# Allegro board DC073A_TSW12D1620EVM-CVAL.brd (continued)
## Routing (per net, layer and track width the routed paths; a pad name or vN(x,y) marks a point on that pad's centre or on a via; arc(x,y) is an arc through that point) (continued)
DID4-: length 81.3
  L08_SIG2 w0.076: v1(85.22,93.6) 85.22,94.01 85.34,94.13 85.66,94.13 86.04,94.51 86.04,99.3 87.83,101.09 99.63,101.09 102.03,98.69 104.28,98.69 104.57,98.99 104.57,99.73 104.72,99.89 105.26,99.89 105.41,99.73 105.41,98.99 105.7,98.69 106.44,98.69 106.73,98.99 106.73,99.73 106.88,99.89 107.42,99.89 107.57,99.73 107.57,98.99 107.86,98.69 108.6,98.69 108.89,98.99 108.89,99.73 109.04,99.89 109.58,99.89 109.73,99.73 109.73,98.99 110.02,98.69 110.76,98.69 111.05,98.99 111.05,99.73 111.2,99.89 111.74,99.89 111.89,99.73 111.89,98.99 112.18,98.69 112.91,98.69 113.21,98.99 113.21,99.73 113.36,99.89 113.89,99.89 114.05,99.73 114.05,98.99 114.34,98.69 115.07,98.69 115.37,98.99 115.37,99.73 115.52,99.89 116.05,99.89 116.21,99.73 116.21,98.99 116.5,98.69 117.23,98.69 117.53,98.99 117.53,99.73 117.68,99.89 118.21,99.89 118.36,99.73 118.36,98.99 118.66,98.69 119.39,98.69 119.69,98.99 119.69,99.73 119.84,99.89 120.37,99.89 120.52,99.73 120.52,98.99 120.82,98.69 121.55,98.69 121.84,98.99 121.84,99.73 122,99.89 122.53,99.89 123.72,98.69 126.62,98.69 130.09,95.22 136.68,95.22 137.05,94.85 137.05,93.15 137.51,92.69 138.99,92.69 139.06,92.61 v1(139.06,92.18)
DID5+: length 81.4
  L05_SIG1 w0.076: v1(140.34,94.72) 140.34,94.28 140.26,94.2 139.77,94.2 139.48,93.92 139.48,93.27 139.16,92.95 138.79,92.95 138.21,92.38 138.21,92 137.87,91.66 131.32,91.66 128.28,94.69 128.28,102.23 124.65,105.87 111.13,105.87 110.84,105.57 110.84,105.37 110.69,105.22 110.15,105.22 110,105.37 110,105.57 109.71,105.87 108.97,105.87 108.68,105.57 108.68,105.37 108.53,105.22 107.99,105.22 107.84,105.37 107.84,105.57 107.55,105.87 106.81,105.87 106.52,105.57 106.52,105.37 106.37,105.22 105.84,105.22 105.68,105.37 105.68,105.57 105.39,105.87 104.66,105.87 104.36,105.57 104.36,105.37 104.21,105.22 103.68,105.22 103.52,105.37 103.52,105.57 103.23,105.87 102.62,105.87 101.41,104.66 92.27,104.66 90.34,106.59 89,106.59 88.28,105.87 88.28,96.06 87.86,95.64 86.58,95.64 86.49,95.74 v1(86.49,96.14)
DID5-: length 81.4
  L05_SIG1 w0.076: v1(86.49,94.87) 86.49,95.27 86.62,95.4 87.96,95.4 88.52,95.96 88.52,105.77 89.1,106.35 90.24,106.35 92.17,104.42 101.51,104.42 102.72,105.63 103.13,105.63 103.28,105.47 103.28,105.27 103.58,104.98 104.31,104.98 104.6,105.27 104.6,105.47 104.76,105.63 105.29,105.63 105.44,105.47 105.44,105.27 105.74,104.98 106.47,104.98 106.76,105.27 106.76,105.47 106.91,105.63 107.45,105.63 107.6,105.47 107.6,105.27 107.89,104.98 108.63,104.98 108.92,105.27 108.92,105.47 109.07,105.63 109.61,105.63 109.76,105.47 109.76,105.27 110.05,104.98 110.79,104.98 111.08,105.27 111.08,105.47 111.23,105.63 124.55,105.63 128.04,102.13 128.04,94.59 131.22,91.41 137.97,91.41 138.46,91.9 138.46,92.28 138.89,92.71 139.26,92.71 139.73,93.17 139.73,93.82 139.87,93.96 140.26,93.96 140.34,93.88 v1(140.34,93.45)
DID6+: length 81.3
  L08_SIG2 w0.076: v1(87.76,97.41) 87.76,97.01 87.86,96.91 89.16,96.91 89.48,97.23 89.48,97.95 90.35,98.82 97.38,98.82 100.62,95.58 101.89,95.58 102.18,95.29 102.18,93.1 102.34,92.95 102.87,92.95 103.02,93.1 103.02,95.29 103.31,95.58 104.05,95.58 104.34,95.29 104.34,93.1 104.49,92.95 105.03,92.95 105.18,93.1 105.18,95.29 105.47,95.58 106.21,95.58 106.5,95.29 106.5,93.1 106.65,92.95 107.19,92.95 107.34,93.1 107.34,95.29 107.63,95.58 108.37,95.58 108.66,95.29 108.66,93.1 108.81,92.95 109.35,92.95 109.5,93.1 109.5,95.29 109.79,95.58 110.53,95.58 110.82,95.29 110.82,93.1 110.97,92.95 111.5,92.95 111.66,93.1 111.66,95.21 112.79,96.34 113.83,96.34 114.12,96.05 114.12,95.73 114.27,95.58 114.8,95.58 114.96,95.73 114.96,96.05 115.25,96.34 115.98,96.34 116.28,96.05 116.28,95.73 116.43,95.58 116.96,95.58 117.12,95.73 117.12,96.05 117.41,96.34 118.14,96.34 118.44,96.05 118.44,95.73 118.59,95.58 119.12,95.58 119.28,95.73 119.28,96.05 119.57,96.34 120.3,96.34 120.6,96.05 120.6,95.73 120.75,95.58 121.28,95.58 121.43,95.73 121.43,96.05 121.73,96.34 122.46,96.34 122.76,96.05 122.76,95.73 122.91,95.58 123.44,95.58 123.59,95.73 123.59,96.05 123.89,96.34 124.62,96.34 124.91,96.05 124.91,95.73 125.07,95.58 125.65,95.58 130.84,90.39 133.91,90.39 133.99,90.47 v1(133.99,90.91)
DID6-: length 81.3
  L08_SIG2 w0.076: v1(87.76,96.14) 87.76,96.54 87.88,96.67 89.26,96.67 89.73,97.13 89.73,97.85 90.45,98.58 97.28,98.58 100.52,95.34 101.79,95.34 101.94,95.19 101.94,93 102.23,92.71 102.97,92.71 103.26,93 103.26,95.19 103.41,95.34 103.95,95.34 104.1,95.19 104.1,93 104.39,92.71 105.13,92.71 105.42,93 105.42,95.19 105.57,95.34 106.11,95.34 106.26,95.19 106.26,93 106.55,92.71 107.29,92.71 107.58,93 107.58,95.19 107.73,95.34 108.27,95.34 108.42,95.19 108.42,93 108.71,92.71 109.45,92.71 109.74,93 109.74,95.19 109.89,95.34 110.42,95.34 110.58,95.19 110.58,93 110.87,92.71 111.6,92.71 111.9,93 111.9,95.11 112.89,96.1 113.73,96.1 113.88,95.95 113.88,95.63 114.17,95.34 114.91,95.34 115.2,95.63 115.2,95.95 115.35,96.1 115.88,96.1 116.04,95.95 116.04,95.63 116.33,95.34 117.06,95.34 117.36,95.63 117.36,95.95 117.51,96.1 118.04,96.1 118.2,95.95 118.2,95.63 118.49,95.34 119.22,95.34 119.52,95.63 119.52,95.95 119.67,96.1 120.2,96.1 120.35,95.95 120.35,95.63 120.65,95.34 121.38,95.34 121.68,95.63 121.68,95.95 121.83,96.1 122.36,96.1 122.51,95.95 122.51,95.63 122.81,95.34 123.54,95.34 123.83,95.63 123.83,95.95 123.99,96.1 124.52,96.1 124.67,95.95 124.67,95.63 124.97,95.34 125.55,95.34 130.74,90.15 133.91,90.15 133.99,90.07 v1(133.99,89.64)
DID7+: length 81.3
  L08_SIG2 w0.076: v1(135.25,92.18) 135.25,91.74 135.18,91.66 134.81,91.66 134.53,91.39 134.53,89.56 134.11,89.14 129.84,89.14 127.01,91.97 125.61,91.97 125.46,92.13 125.46,93.7 125.02,94.13 113.4,94.13 113.11,93.84 113.11,93.11 113.4,92.81 123.98,92.81 124.13,92.66 124.13,92.13 123.98,91.97 101.89,91.97 96.92,96.94 95.92,96.94 95.9,96.95 90.22,96.95 89.55,96.28 89.55,94.57 89.34,94.37 87.86,94.37 87.76,94.47 v1(87.76,94.87)
DID7-: length 81.4
  L08_SIG2 w0.076: v1(87.76,93.6) 87.76,94 87.86,94.1 89.45,94.1 89.81,94.46 89.81,96.2 90.3,96.69 95.9,96.69 95.92,96.7 96.82,96.7 101.79,91.73 124.08,91.73 124.38,92.03 124.38,92.76 124.08,93.05 113.5,93.05 113.35,93.21 113.35,93.74 113.5,93.89 124.92,93.89 125.21,93.6 125.21,92.03 125.51,91.73 126.91,91.73 129.74,88.9 134.21,88.9 134.77,89.46 134.77,91.29 134.91,91.42 135.18,91.42 135.25,91.34 v1(135.25,90.91)
DID8+: length 81.2
  L05_SIG1 w0.076: v1(89.03,96.14) 89.03,95.79 89.15,95.67 89.38,95.67 89.57,95.86 89.57,102.64 90.2,103.26 107.71,103.26 108.39,103.95 108.39,104.1 108.69,104.39 109.42,104.39 109.71,104.1 109.71,103.95 109.87,103.8 111.55,103.8 111.7,103.95 111.7,104.76 111.99,105.05 112.73,105.05 113.02,104.76 113.02,103.95 113.17,103.8 113.71,103.8 113.86,103.95 113.86,104.76 114.15,105.05 114.88,105.05 115.18,104.76 115.18,103.95 115.33,103.8 115.86,103.8 116.02,103.95 116.02,104.76 116.31,105.05 117.04,105.05 117.34,104.76 117.34,103.95 117.49,103.8 118.02,103.8 118.18,103.95 118.18,104.76 118.47,105.05 119.2,105.05 119.5,104.76 119.5,103.95 119.65,103.8 120.18,103.8 120.33,103.95 120.33,104.76 120.63,105.05 121.36,105.05 121.67,104.75 121.67,103.94 121.81,103.8 122.34,103.8 122.49,103.95 122.49,104.76 122.79,105.05 123.52,105.05 123.81,104.76 123.81,103.95 123.97,103.8 124.75,103.8 126.78,101.77 126.78,94.44 130.82,90.4 137.21,90.4 138.49,89.12 138.99,89.12 139.06,89.2 v1(139.06,89.64)
DID8-: length 81.3
  L05_SIG1 w0.076: v1(139.06,88.37) 139.06,88.8 138.99,88.88 138.39,88.88 137.11,90.16 130.72,90.16 126.54,94.34 126.54,101.67 124.65,103.56 123.87,103.56 123.57,103.85 123.57,104.66 123.42,104.81 122.89,104.81 122.73,104.66 122.73,103.85 122.44,103.56 121.71,103.56 121.42,103.84 121.42,104.65 121.26,104.81 120.73,104.81 120.58,104.66 120.58,103.85 120.28,103.56 119.55,103.56 119.26,103.85 119.26,104.66 119.1,104.81 118.57,104.81 118.42,104.66 118.42,103.85 118.12,103.56 117.39,103.56 117.1,103.85 117.1,104.66 116.94,104.81 116.41,104.81 116.26,104.66 116.26,103.85 115.96,103.56 115.23,103.56 114.94,103.85 114.94,104.66 114.78,104.81 114.25,104.81 114.1,104.66 114.1,103.85 113.81,103.56 113.07,103.56 112.78,103.85 112.78,104.66 112.63,104.81 112.09,104.81 111.94,104.66 111.94,103.85 111.65,103.56 109.77,103.56 109.47,103.85 109.47,104 109.32,104.15 108.79,104.15 108.63,104 108.63,103.85 107.81,103.02 90.3,103.02 89.81,102.54 89.81,95.76 89.46,95.4 89.13,95.4 89.03,95.3 v1(89.03,94.87)
DID9+: length 81.3
  L05_SIG1 w0.076: v1(90.3,97.41) 90.3,97 90.44,96.86 90.75,96.86 90.83,96.94 90.83,100.99 91.86,102.02 92.7,102.02 93.69,101.03 94.06,101.03 94.37,101.34 94.37,101.73 94.67,102.02 95.4,102.02 95.69,101.73 95.69,101.18 95.85,101.03 96.38,101.03 96.53,101.18 96.53,101.73 96.83,102.02 97.56,102.02 97.85,101.73 97.85,101.18 98.01,101.03 98.54,101.03 98.69,101.18 98.69,101.73 98.99,102.02 99.72,102.02 100.01,101.73 100.01,101.18 100.16,101.03 100.7,101.03 100.85,101.18 100.85,101.73 101.14,102.02 101.88,102.02 102.17,101.73 102.17,101.18 102.32,101.03 102.86,101.03 103.01,101.18 103.01,101.73 103.3,102.02 104.04,102.02 104.33,101.73 104.33,101.18 104.48,101.03 105.02,101.03 105.17,101.18 105.17,101.73 105.46,102.02 106.2,102.02 106.49,101.73 106.49,101.18 106.64,101.03 107.18,101.03 107.33,101.18 107.33,101.73 107.62,102.02 108.35,102.02 108.65,101.73 108.65,101.18 108.8,101.03 109.33,101.03 109.49,101.18 109.49,101.73 109.78,102.02 110.51,102.02 110.81,101.73 110.81,101.18 110.96,101.03 111.49,101.03 111.65,101.18 111.65,101.73 111.94,102.02 112.67,102.02 112.97,101.73 112.97,101.18 113.12,101.03 113.65,101.03 113.8,101.18 113.8,101.73 114.1,102.02 114.83,102.02 115.13,101.73 115.13,101.18 115.28,101.03 115.81,101.03 116.8,102.02 123.75,102.02 125.16,100.61 125.16,93.93 129.97,89.12 137.08,89.12 138.25,87.95 139.24,87.95 139.53,88.24 139.53,88.76 139.9,89.12 140.26,89.12 140.34,89.2 v1(140.34,89.64)
DID9-: length 81.3
  L05_SIG1 w0.076: v1(140.34,88.37) 140.34,88.8 140.26,88.88 140,88.88 139.78,88.66 139.78,88.14 139.34,87.71 138.15,87.71 136.98,88.87 129.87,88.87 124.92,93.83 124.92,100.51 123.65,101.78 116.9,101.78 115.91,100.79 115.18,100.79 114.88,101.08 114.88,101.63 114.73,101.78 114.2,101.78 114.05,101.63 114.05,101.08 113.75,100.79 113.02,100.79 112.72,101.08 112.72,101.63 112.57,101.78 112.04,101.78 111.89,101.63 111.89,101.08 111.59,100.79 110.86,100.79 110.57,101.08 110.57,101.63 110.41,101.78 109.88,101.78 109.73,101.63 109.73,101.08 109.43,100.79 108.7,100.79 108.41,101.08 108.41,101.63 108.25,101.78 107.72,101.78 107.57,101.63 107.57,101.08 107.28,100.79 106.54,100.79 106.25,101.08 106.25,101.63 106.1,101.78 105.56,101.78 105.41,101.63 105.41,101.08 105.12,100.79 104.38,100.79 104.09,101.08 104.09,101.63 103.94,101.78 103.4,101.78 103.25,101.63 103.25,101.08 102.96,100.79 102.22,100.79 101.93,101.08 101.93,101.63 101.78,101.78 101.24,101.78 101.09,101.63 101.09,101.08 100.8,100.79 100.06,100.79 99.77,101.08 99.77,101.63 99.62,101.78 99.09,101.78 98.93,101.63 98.93,101.08 98.64,100.79 97.91,100.79 97.61,101.08 97.61,101.63 97.46,101.78 96.93,101.78 96.77,101.63 96.77,101.08 96.48,100.79 95.75,100.79 95.45,101.08 95.45,101.63 95.3,101.78 94.77,101.78 94.61,101.63 94.61,101.24 94.16,100.79 93.59,100.79 92.6,101.78 91.96,101.78 91.07,100.89 91.07,96.84 90.85,96.62 90.37,96.62 90.3,96.55 v1(90.3,96.14)
DID10+: length 81.1
  L08_SIG2 w0.076: v1(91.57,96.14) 91.1,95.67 91.1,95.53 91.26,95.37 91.26,95.08 91.11,94.93 91.11,94.65 91.41,94.35 97.68,94.35 103.61,88.42 106.03,88.42 106.24,88.62 106.24,90.28 106.53,90.58 121.83,90.58 122.12,90.28 122.12,89.55 121.85,89.28 107.73,89.28 107.56,89.1 107.56,88.57 107.71,88.42 118.74,88.42 118.77,88.38 128.45,88.38 130.24,86.58 133.91,86.58 133.99,86.66 v1(133.99,87.1)
DID10-: length 81.3
  L08_SIG2 w0.076: v1(133.99,85.83) 133.99,86.26 133.91,86.34 130.14,86.34 128.35,88.14 118.67,88.14 118.64,88.18 107.61,88.18 107.32,88.47 107.32,89.2 107.63,89.52 121.75,89.52 121.88,89.65 121.88,90.18 121.73,90.34 106.63,90.34 106.48,90.18 106.48,88.52 106.13,88.18 103.51,88.18 97.58,94.11 91.31,94.11 90.87,94.55 90.87,95.03 91.02,95.18 91.02,95.27 90.95,95.34 90.77,95.34 v1(90.3,94.87)
DID11+: length 81.3
  L05_SIG1 w0.076: v1(135.25,88.37) 135.25,87.93 135.18,87.85 128.59,87.85 121.72,94.72 121.72,94.94 124.02,97.23 124.02,97.65 123.5,98.17 123.09,98.17 120.79,95.87 120.57,95.87 120.2,96.25 120.2,96.46 122.49,98.76 122.49,99.17 121.97,99.69 121.56,99.69 119.26,97.4 119.05,97.4 118.67,97.78 118.67,97.99 120.96,100.29 120.96,100.7 120.45,101.22 120.03,101.22 117.73,98.92 117.52,98.92 116.79,99.66 116.01,99.66 115.54,99.18 115.54,98.62 115.38,98.46 114.85,98.46 114.7,98.62 114.7,99.36 114.4,99.66 113.67,99.66 113.38,99.36 113.38,98.62 113.22,98.46 112.69,98.46 112.54,98.62 112.54,99.36 112.25,99.66 111.51,99.66 111.22,99.36 111.22,98.62 111.07,98.46 110.53,98.46 110.38,98.62 110.38,99.36 110.09,99.66 109.35,99.66 109.06,99.36 109.06,98.62 108.91,98.46 108.37,98.46 108.22,98.62 108.22,99.36 107.93,99.66 107.19,99.66 106.9,99.36 106.9,98.62 106.75,98.46 106.21,98.46 106.06,98.62 106.06,99.36 105.77,99.66 105.03,99.66 104.74,99.36 104.74,98.62 104.59,98.46 104.06,98.46 103.9,98.62 103.9,99.36 103.61,99.66 93.79,99.66 93.33,99.2 93.33,97.55 93.19,97.41 v1(92.84,97.41)
DID11-: length 81.3
  L05_SIG1 w0.076: v1(94.11,97.41) 93.7,97.41 93.57,97.54 93.57,99.1 93.89,99.42 94.21,99.42 94.32,99.3 94.32,99.25 94.43,99.14 94.59,99.14 94.7,99.25 94.7,99.3 94.82,99.42 103.51,99.42 103.66,99.26 103.66,98.52 103.96,98.22 104.69,98.22 104.98,98.52 104.98,99.26 105.13,99.42 105.67,99.42 105.82,99.26 105.82,98.52 106.11,98.22 106.85,98.22 107.14,98.52 107.14,99.26 107.29,99.42 107.83,99.42 107.98,99.26 107.98,98.52 108.27,98.22 109.01,98.22 109.3,98.52 109.3,99.26 109.45,99.42 109.99,99.42 110.14,99.26 110.14,98.52 110.43,98.22 111.17,98.22 111.46,98.52 111.46,99.26 111.61,99.42 112.15,99.42 112.3,99.26 112.3,98.52 112.59,98.22 113.32,98.22 113.62,98.52 113.62,99.26 113.77,99.42 114.3,99.42 114.46,99.26 114.46,98.52 114.75,98.22 115.48,98.22 115.78,98.52 115.78,99.08 116.11,99.42 116.69,99.42 117.42,98.68 117.83,98.68 120.13,100.98 120.35,100.98 120.72,100.6 120.72,100.39 118.43,98.09 118.43,97.68 118.95,97.16 119.36,97.16 121.66,99.45 121.87,99.45 122.25,99.07 122.25,98.86 119.96,96.56 119.96,96.15 120.47,95.63 120.89,95.63 123.19,97.92 123.4,97.92 123.78,97.55 123.78,97.33 121.48,95.04 121.48,94.62 128.49,87.61 135.18,87.61 135.25,87.53 v1(135.25,87.1)
DQ0+: length 81.1
  L08_SIG2 w0.076: v1(92.84,74.55) 92.34,75.05 92.19,75.05 92.12,74.98 92.12,74.88 92.2,74.8 92.2,73.21 92.72,72.7 92.93,72.7 93.13,72.5 93.13,72.28 95.36,70.05 95.55,70.05 95.71,70.21 95.96,70.21 96.11,70.05 96.53,70.05 98.29,71.81 99.54,71.81 99.83,71.51 99.83,70.79 99.98,70.64 100.52,70.64 100.67,70.79 100.67,71.51 100.96,71.81 101.7,71.81 101.99,71.51 101.99,70.79 102.14,70.64 102.68,70.64 102.83,70.79 102.83,71.51 103.12,71.81 103.86,71.81 104.15,71.51 104.15,70.79 104.3,70.64 104.84,70.64 104.99,70.79 104.99,71.51 105.28,71.81 106.02,71.81 106.31,71.51 106.31,70.79 106.46,70.64 106.99,70.64 107.15,70.79 107.15,71.51 107.44,71.81 108.17,71.81 108.47,71.51 108.47,70.79 108.62,70.64 109.15,70.64 109.31,70.79 109.31,71.51 109.6,71.81 110.33,71.81 110.63,71.51 110.63,70.79 110.78,70.64 111.31,70.64 111.47,70.79 111.47,71.51 111.76,71.81 112.49,71.81 112.79,71.51 112.79,70.79 112.94,70.64 113.47,70.64 113.62,70.79 113.62,71.51 113.92,71.81 114.65,71.81 114.95,71.51 114.95,70.79 115.1,70.64 115.63,70.64 115.78,70.79 115.78,71.51 116.08,71.81 116.81,71.81 117.1,71.51 117.1,70.79 117.26,70.64 117.79,70.64 117.94,70.79 117.94,71.51 118.24,71.81 118.97,71.81 119.26,71.51 119.26,70.79 119.42,70.64 119.95,70.64 120.1,70.79 120.1,71.51 120.39,71.81 121.13,71.81 121.42,71.51 121.42,70.79 121.57,70.64 122.11,70.64 122.26,70.79 122.26,71.51 122.55,71.81 123.29,71.81 123.58,71.51 123.58,70.79 123.73,70.64 124.27,70.64 124.42,70.79 124.42,71.51 124.71,71.81 125.45,71.81 125.74,71.51 125.74,70.79 125.89,70.64 126.43,70.64 126.58,70.79 126.58,71.51 126.87,71.81 127.61,71.81 128.77,70.64 129.28,70.64 129.87,70.05 134.14,70.05 134.47,70.38 134.47,70.87 134.29,71.05 134.29,71.25 134.47,71.43 134.47,73.43 134.25,73.65 132.39,73.65 131.94,74.09 131.94,76.12 132.24,76.42 132.64,76.42 132.72,76.5 v1(132.72,76.94)
DQ0-: length 81.3
  L08_SIG2 w0.076: v1(132.72,75.67) 132.72,76.1 132.64,76.18 132.34,76.18 132.18,76.02 132.18,74.19 132.49,73.89 134.35,73.89 134.71,73.53 134.71,70.28 134.24,69.81 129.77,69.81 129.18,70.4 128.67,70.4 127.51,71.56 126.97,71.56 126.82,71.41 126.82,70.69 126.53,70.4 125.79,70.4 125.5,70.69 125.5,71.41 125.35,71.56 124.81,71.56 124.66,71.41 124.66,70.69 124.37,70.4 123.63,70.4 123.34,70.69 123.34,71.41 123.19,71.56 122.65,71.56 122.5,71.41 122.5,70.69 122.21,70.4 121.47,70.4 121.18,70.69 121.18,71.41 121.03,71.56 120.5,71.56 120.34,71.41 120.34,70.69 120.05,70.4 119.32,70.4 119.02,70.69 119.02,71.41 118.87,71.56 118.34,71.56 118.18,71.41 118.18,70.69 117.89,70.4 117.16,70.4 116.86,70.69 116.86,71.41 116.71,71.56 116.18,71.56 116.02,71.41 116.02,70.69 115.73,70.4 115,70.4 114.7,70.69 114.7,71.41 114.55,71.56 114.02,71.56 113.87,71.41 113.87,70.69 113.57,70.4 112.84,70.4 112.54,70.69 112.54,71.41 112.39,71.56 111.86,71.56 111.71,71.41 111.71,70.69 111.41,70.4 110.68,70.4 110.39,70.69 110.39,71.41 110.23,71.56 109.7,71.56 109.55,71.41 109.55,70.69 109.25,70.4 108.52,70.4 108.23,70.69 108.23,71.41 108.07,71.56 107.54,71.56 107.39,71.41 107.39,70.69 107.1,70.4 106.36,70.4 106.07,70.69 106.07,71.41 105.92,71.56 105.38,71.56 105.23,71.41 105.23,70.69 104.94,70.4 104.2,70.4 103.91,70.69 103.91,71.41 103.76,71.56 103.22,71.56 103.07,71.41 103.07,70.69 102.78,70.4 102.04,70.4 101.75,70.69 101.75,71.41 101.6,71.56 101.06,71.56 100.91,71.41 100.91,70.69 100.62,70.4 99.88,70.4 99.59,70.69 99.59,71.41 99.44,71.56 98.39,71.56 96.63,69.81 95.26,69.81 91.96,73.11 91.96,74.7 91.88,74.78 91.88,75.08 92.04,75.24 92.04,75.35 v1(91.57,75.82)
DQ1+: length 81.3
  L08_SIG2 w0.076: v1(136.53,79.48) 136.53,79.12 136.37,78.97 132.86,78.97 131.48,77.6 131.17,77.6 130.63,77.06 130.63,75.12 130.05,74.54 129.49,74.54 129,75.03 129,75.68 128.09,76.58 112.08,76.58 111.79,76.29 111.79,75.55 112.08,75.26 127.52,75.26 127.68,75.11 127.68,74.57 127.52,74.42 98.15,74.42 97.36,75.21 94.83,75.21 94.61,74.99 94.61,74.65 94.51,74.55 v1(94.11,74.55)
DQ1-: length 81.2
  L08_SIG2 w0.076: v1(136.53,78.21) 136.53,78.64 136.44,78.73 132.96,78.73 131.58,77.36 131.27,77.36 130.87,76.96 130.87,75.02 130.15,74.3 129.39,74.3 128.76,74.93 128.76,75.58 127.99,76.34 112.18,76.34 112.03,76.19 112.03,75.65 112.18,75.5 127.62,75.5 127.92,75.21 127.92,74.47 127.62,74.18 98.05,74.18 97.26,74.97 96.85,74.97 96.74,74.86 96.74,74.81 96.63,74.7 96.47,74.7 96.36,74.81 96.36,74.86 96.25,74.97 94.93,74.97 94.88,74.91 94.88,74.65 94.98,74.55 v1(95.38,74.55)
DQ2+: length 81.3
  L08_SIG2 w0.076: v1(137.79,80.75) 137.79,80.47 137.62,80.29 132.7,80.29 130.09,77.67 112.95,77.67 112.29,78.33 111,78.33 110.61,77.94 110.61,75.65 110.46,75.5 109.92,75.5 109.77,75.65 109.77,78.38 109.48,78.68 108.74,78.68 108.45,78.38 108.45,75.65 108.3,75.5 107.76,75.5 107.61,75.65 107.61,78.38 107.32,78.68 106.58,78.68 106.29,78.38 106.29,75.65 106.14,75.5 105.6,75.5 105.45,75.65 105.45,78.38 105.16,78.68 104.42,78.68 104.13,78.38 104.13,75.65 103.98,75.5 103.45,75.5 103.31,75.63 103.31,78.36 103,78.68 102.3,78.68 101.97,78.35 101.97,75.65 101.82,75.5 101.29,75.5 101.13,75.65 101.13,78.38 100.84,78.68 100.11,78.68 99.81,78.38 99.81,75.65 99.66,75.5 99.13,75.5 98.98,75.65 98.98,78.38 98.68,78.68 97.82,78.68 95.73,76.59 94.96,76.59 94.61,76.24 94.61,75.92 94.51,75.82 v1(94.11,75.82)
DQ2-: length 81.2
  L08_SIG2 w0.076: v1(137.79,79.48) 137.79,79.88 137.63,80.05 132.8,80.05 130.19,77.43 112.85,77.43 112.19,78.09 111.1,78.09 110.85,77.84 110.85,75.55 110.56,75.26 109.82,75.26 109.53,75.55 109.53,78.28 109.38,78.44 108.84,78.44 108.69,78.28 108.69,75.55 108.4,75.26 107.66,75.26 107.37,75.55 107.37,78.28 107.22,78.44 106.68,78.44 106.53,78.28 106.53,75.55 106.24,75.26 105.5,75.26 105.21,75.55 105.21,78.28 105.06,78.44 104.53,78.44 104.37,78.28 104.37,75.55 104.08,75.26 103.35,75.26 103.07,75.53 103.07,78.26 102.9,78.44 102.4,78.44 102.21,78.25 102.21,75.55 101.92,75.26 101.19,75.26 100.89,75.55 100.89,78.28 100.74,78.44 100.21,78.44 100.05,78.28 100.05,75.55 99.76,75.26 99.03,75.26 98.73,75.55 98.73,78.28 98.58,78.44 97.92,78.44 96.41,76.92 96.41,76.64 96.28,76.51 96,76.51 95.83,76.35 95.09,76.35 94.88,76.13 94.88,75.92 94.98,75.82 v1(95.38,75.82)
DQ3+: length 81.1
  L08_SIG2 w0.076: v1(136.53,75.67) 136.53,75.34 136.35,75.16 135.97,75.16 135.75,74.94 135.75,69.05 135.5,68.8 128.9,68.8 128.82,68.87 128.82,68.88 128.74,68.96 128.52,68.96 128.44,68.88 128.44,68.87 128.36,68.8 127.9,68.8 127.75,68.95 127.75,69.48 127.45,69.77 126.72,69.77 126.43,69.48 126.43,68.95 126.27,68.8 125.74,68.8 125.59,68.95 125.59,69.48 125.3,69.77 124.56,69.77 124.27,69.48 124.27,68.95 124.12,68.8 123.58,68.8 123.43,68.95 123.43,69.48 123.14,69.77 122.4,69.77 122.11,69.48 122.11,68.95 121.96,68.8 121.42,68.8 121.27,68.95 121.27,69.48 120.98,69.77 120.24,69.77 119.95,69.48 119.95,68.95 119.8,68.8 119.26,68.8 119.11,68.95 119.11,69.48 118.82,69.77 118.08,69.77 117.79,69.48 117.79,68.95 117.64,68.8 117.11,68.8 116.95,68.95 116.95,69.48 116.66,69.77 115.93,69.77 115.63,69.48 115.63,68.95 115.48,68.8 114.95,68.8 114.79,68.95 114.79,69.48 114.5,69.77 113.77,69.77 113.47,69.48 113.47,68.95 113.32,68.8 112.79,68.8 112.63,68.95 112.63,69.48 112.34,69.77 111.61,69.77 111.31,69.48 111.31,68.95 111.16,68.8 110.63,68.8 110.48,68.95 110.48,69.48 110.18,69.77 109.45,69.77 109.15,69.48 109.15,68.95 109,68.8 108.47,68.8 108.32,68.95 108.32,69.48 108.02,69.77 107.29,69.77 107,69.48 107,68.95 106.84,68.8 106.31,68.8 106.16,68.95 106.16,69.48 105.86,69.77 105.13,69.77 104.84,69.48 104.84,68.95 104.68,68.8 104.15,68.8 104,68.95 104,69.48 103.71,69.77 102.97,69.77 102.68,69.48 102.68,68.95 102.53,68.8 101.99,68.8 101.84,68.95 101.84,69.48 101.55,69.77 100.81,69.77 100.52,69.48 100.52,68.95 100.37,68.8 99.83,68.8 99.68,68.95 99.68,69.48 99.39,69.77 98.65,69.77 98.36,69.48 98.36,69.31 97.55,68.5 96.36,68.5 96.21,68.66 95.98,68.66 95.83,68.5 95.54,68.5 91.87,72.18 91.87,72.34 91.68,72.53 91.51,72.53 91.05,73 91.05,76.24 91.12,76.32 91.19,76.32 91.26,76.4 91.26,76.62 91.19,76.7 91.12,76.7 91.05,76.78 91.05,77.37 91.29,77.62 92.71,77.62 92.84,77.49 v1(92.84,77.09)
DQ3-: length 81.3
  L08_SIG2 w0.076: v1(136.53,74.4) 136.53,74.78 136.39,74.92 136.07,74.92 135.99,74.84 135.99,68.95 135.6,68.55 127.8,68.55 127.51,68.85 127.51,69.38 127.35,69.53 126.82,69.53 126.67,69.38 126.67,68.85 126.37,68.55 125.64,68.55 125.35,68.85 125.35,69.38 125.2,69.53 124.66,69.53 124.51,69.38 124.51,68.85 124.22,68.55 123.48,68.55 123.19,68.85 123.19,69.38 123.04,69.53 122.5,69.53 122.35,69.38 122.35,68.85 122.06,68.55 121.32,68.55 121.03,68.85 121.03,69.38 120.88,69.53 120.34,69.53 120.19,69.38 120.19,68.85 119.9,68.55 119.16,68.55 118.87,68.85 118.87,69.38 118.72,69.53 118.18,69.53 118.03,69.38 118.03,68.85 117.74,68.55 117.01,68.55 116.71,68.85 116.71,69.38 116.56,69.53 116.03,69.53 115.87,69.38 115.87,68.85 115.58,68.55 114.85,68.55 114.55,68.85 114.55,69.38 114.4,69.53 113.87,69.53 113.71,69.38 113.71,68.85 113.42,68.55 112.69,68.55 112.39,68.85 112.39,69.38 112.24,69.53 111.71,69.53 111.56,69.38 111.56,68.85 111.26,68.55 110.53,68.55 110.23,68.85 110.23,69.38 110.08,69.53 109.55,69.53 109.4,69.38 109.4,68.85 109.1,68.55 108.37,68.55 108.08,68.85 108.08,69.38 107.92,69.53 107.39,69.53 107.24,69.38 107.24,68.85 106.94,68.55 106.21,68.55 105.92,68.85 105.92,69.38 105.76,69.53 105.23,69.53 105.08,69.38 105.08,68.85 104.78,68.55 104.05,68.55 103.76,68.85 103.76,69.38 103.61,69.53 103.07,69.53 102.92,69.38 102.92,68.85 102.63,68.55 101.89,68.55 101.6,68.85 101.6,69.38 101.45,69.53 100.91,69.53 100.76,69.38 100.76,68.85 100.47,68.55 99.73,68.55 99.44,68.85 99.44,69.38 99.29,69.53 98.75,69.53 98.6,69.38 98.6,69.21 97.65,68.26 95.44,68.26 90.81,72.9 90.81,77.47 91.19,77.86 92.74,77.86 92.84,77.96 v1(92.84,78.36)
DQ4+: length 81.3
  L08_SIG2 w0.076: v1(137.79,76.94) 137.79,76.5 137.72,76.42 137.48,76.42 137.22,76.68 137.22,78.23 137.62,78.63 137.91,78.63 138.61,79.32 138.61,80.88 137.95,81.55 132.84,81.55 130.1,78.8 116.73,78.8 116.48,79.04 116.48,79.4 116.73,79.64 129.25,79.64 129.46,79.86 129.46,80.75 129.25,80.96 115.11,80.96 113.64,79.49 97.08,79.49 95.44,77.85 95.01,77.85 94.61,77.44 94.61,77.19 94.51,77.09 v1(94.11,77.09)
DQ4-: length 81.3
  L08_SIG2 w0.076: v1(137.79,75.67) 137.79,76.1 137.72,76.18 137.38,76.18 136.98,76.58 136.98,78.33 137.52,78.87 137.81,78.87 138.37,79.42 138.37,79.91 138.25,80.02 138.25,80.33 138.37,80.44 138.37,80.78 137.85,81.31 133.56,81.31 133.44,81.18 133.34,81.18 133.21,81.31 132.94,81.31 130.2,78.56 116.63,78.56 116.24,78.94 116.24,79.5 116.63,79.88 129.15,79.88 129.22,79.96 129.22,80.64 129.15,80.72 115.21,80.72 113.74,79.25 97.18,79.25 96.34,78.41 96.34,78.08 96.19,77.93 95.86,77.93 95.54,77.61 95.11,77.61 94.88,77.37 94.88,77.19 94.98,77.09 v1(95.38,77.09)
DQ5+: length 81.3
  L05_SIG1 w0.076: v1(131.44,71.86) 131.44,71.42 131.52,71.34 131.96,71.34 132.27,71.03 132.27,70.13 131.91,69.77 130.54,69.77 129.76,68.99 129.76,67.11 128.73,66.08 128,66.08 127.7,66.37 127.7,68.08 127.55,68.24 114.49,68.24 114.34,68.08 114.34,67.55 114.49,67.4 126.57,67.4 126.86,67.11 126.86,66.37 126.57,66.08 99.42,66.08 94.62,70.87 94.62,78.28 94.55,78.36 v1(94.11,78.36)
DQ5-: length 81.2
  L05_SIG1 w0.076: v1(131.44,70.59) 131.44,71.02 131.52,71.1 131.86,71.1 132.03,70.93 132.03,70.82 131.93,70.71 131.93,70.46 132.03,70.36 132.03,70.23 131.81,70.02 131.08,70.02 131.01,70.08 131.01,70.23 130.9,70.34 130.79,70.34 130.68,70.23 130.68,70.08 130.62,70.02 130.44,70.02 129.51,69.09 129.51,67.21 129.22,66.92 129.07,66.92 129.03,66.95 128.88,66.95 128.76,66.84 128.76,66.68 128.8,66.65 128.8,66.49 128.63,66.32 128.1,66.32 127.94,66.47 127.94,68.18 127.65,68.48 114.39,68.48 114.1,68.18 114.1,67.45 114.39,67.16 126.47,67.16 126.62,67.01 126.62,66.47 126.47,66.32 100.64,66.32 100.44,66.52 100.26,66.52 100.06,66.32 99.52,66.32 95.45,70.39 95.45,70.67 95.32,70.8 95.04,70.8 94.86,70.97 94.86,78.28 94.94,78.36 v1(95.38,78.36)
DQ6+: length 81.1
  L05_SIG1 w0.076: v1(92.84,79.8) 93.28,79.8 93.35,79.88 93.35,80.14 93.67,80.46 96.87,80.46 97.43,79.89 97.43,79.15 96.29,78 96.29,71.61 97.99,69.91 99.39,69.91 99.72,69.58 99.72,67.87 99.87,67.72 112.81,67.72 112.97,67.87 112.97,68.4 112.81,68.55 100.85,68.55 100.56,68.85 100.56,69.58 100.85,69.88 128.5,69.88 131.24,72.61 132.64,72.61 132.72,72.69 v1(132.72,73.13)
DQ6-: length 81.1
  L05_SIG1 w0.076: v1(132.72,71.86) 132.72,72.29 132.64,72.37 131.34,72.37 128.6,69.63 100.95,69.63 100.8,69.48 100.8,68.95 100.95,68.8 112.91,68.8 113.21,68.5 113.21,67.77 112.91,67.48 99.77,67.48 99.48,67.77 99.48,69.48 99.29,69.67 97.89,69.67 96.05,71.51 96.05,78.1 96.65,78.71 96.65,78.98 96.76,79.08 97.03,79.08 97.19,79.25 97.19,79.79 96.77,80.22 95.03,80.22 94.96,80.14 94.96,80.09 94.88,80.01 94.65,80.01 94.57,80.09 94.57,80.14 94.5,80.22 93.77,80.22 93.59,80.04 93.59,79.88 93.67,79.8 v1(94.11,79.8)
DQ7+: length 81.2
  L08_SIG2 w0.076: v1(136.53,71.86) 136.53,71.42 136.6,71.34 136.98,71.34 137.3,71.02 137.3,67.84 136.69,67.23 127.77,67.23 127.35,67.65 126.82,67.65 126.67,67.5 126.67,67.11 126.37,66.81 125.64,66.81 125.35,67.11 125.35,67.5 125.2,67.65 124.66,67.65 124.51,67.5 124.51,67.11 124.22,66.81 123.48,66.81 123.19,67.11 123.19,67.5 123.04,67.65 122.5,67.65 122.35,67.5 122.35,67.11 122.06,66.81 121.32,66.81 121.03,67.11 121.03,67.5 120.88,67.65 120.34,67.65 120.19,67.5 120.19,67.11 119.9,66.81 119.16,66.81 118.87,67.11 118.87,67.5 118.72,67.65 118.18,67.65 118.03,67.5 118.03,67.11 117.74,66.81 117.01,66.81 116.71,67.11 116.71,67.5 116.56,67.65 116.03,67.65 115.87,67.5 115.87,67.11 115.58,66.81 114.85,66.81 114.55,67.11 114.55,67.5 114.4,67.65 113.87,67.65 113.71,67.5 113.71,67.11 113.42,66.81 112.69,66.81 112.39,67.11 112.39,67.5 112.24,67.65 111.71,67.65 111.56,67.5 111.56,67.11 111.26,66.81 110.53,66.81 110.23,67.11 110.23,67.5 110.08,67.65 109.55,67.65 109.4,67.5 109.4,67.11 109.1,66.81 108.37,66.81 108.08,67.11 108.08,67.5 107.92,67.65 107.39,67.65 107.24,67.5 107.24,67.11 106.94,66.81 106.21,66.81 105.92,67.11 105.92,67.5 105.76,67.65 105.23,67.65 105.08,67.5 105.08,67.11 104.78,66.81 104.05,66.81 103.76,67.11 103.76,67.5 103.61,67.65 103.07,67.65 102.92,67.5 102.92,67.11 102.63,66.81 101.89,66.81 101.6,67.11 101.6,67.5 101.45,67.65 100.91,67.65 100.76,67.5 100.76,67.11 100.47,66.81 99.73,66.81 99.44,67.11 99.44,67.5 99.29,67.65 98.73,67.65 98.21,67.13 94.87,67.13 89.5,72.5 89.5,78.43 90.24,79.17 91.84,79.17 92.18,79.51 92.18,80.1 92.06,80.21 92.06,80.8 91.97,80.9 v1(91.57,80.9)
DQ7-: length 81.1
  L08_SIG2 w0.076: v1(92.84,80.9) 92.44,80.9 92.3,80.77 92.3,80.32 92.42,80.2 92.42,79.41 91.94,78.93 90.34,78.93 89.74,78.33 89.74,72.6 90.01,72.33 90.12,72.33 90.13,72.34 90.24,72.34 90.4,72.18 90.4,72.07 90.39,72.06 90.39,71.95 94.97,67.37 95.23,67.37 95.3,67.45 95.3,67.49 95.38,67.56 95.61,67.56 95.68,67.49 95.68,67.45 95.76,67.37 98.11,67.37 98.63,67.89 99.39,67.89 99.68,67.6 99.68,67.21 99.83,67.06 100.37,67.06 100.52,67.21 100.52,67.6 100.81,67.89 101.55,67.89 101.84,67.6 101.84,67.21 101.99,67.06 102.53,67.06 102.68,67.21 102.68,67.6 102.97,67.89 103.71,67.89 104,67.6 104,67.21 104.15,67.06 104.68,67.06 104.84,67.21 104.84,67.6 105.13,67.89 105.86,67.89 106.16,67.6 106.16,67.21 106.31,67.06 106.84,67.06 107,67.21 107,67.6 107.29,67.89 108.02,67.89 108.32,67.6 108.32,67.21 108.47,67.06 109,67.06 109.15,67.21 109.15,67.6 109.45,67.89 110.18,67.89 110.48,67.6 110.48,67.21 110.63,67.06 111.16,67.06 111.31,67.21 111.31,67.6 111.61,67.89 112.34,67.89 112.63,67.6 112.63,67.21 112.79,67.06 113.32,67.06 113.47,67.21 113.47,67.6 113.77,67.89 114.5,67.89 114.79,67.6 114.79,67.21 114.95,67.06 115.48,67.06 115.63,67.21 115.63,67.6 115.93,67.89 116.66,67.89 116.95,67.6 116.95,67.21 117.11,67.06 117.64,67.06 117.79,67.21 117.79,67.6 118.08,67.89 118.82,67.89 119.11,67.6 119.11,67.21 119.26,67.06 119.8,67.06 119.95,67.21 119.95,67.6 120.24,67.89 120.98,67.89 121.27,67.6 121.27,67.21 121.42,67.06 121.96,67.06 122.11,67.21 122.11,67.6 122.4,67.89 123.14,67.89 123.43,67.6 123.43,67.21 123.58,67.06 124.12,67.06 124.27,67.21 124.27,67.6 124.56,67.89 125.3,67.89 125.59,67.6 125.59,67.21 125.74,67.06 126.27,67.06 126.43,67.21 126.43,67.6 126.72,67.89 127.45,67.89 127.87,67.48 128.17,67.48 128.28,67.59 128.55,67.59 128.66,67.48 136.59,67.48 137.06,67.94 137.06,68.33 136.98,68.41 136.91,68.41 136.83,68.49 136.83,68.72 136.91,68.79 136.98,68.79 137.06,68.87 137.06,69.7 136.98,69.78 136.83,69.78 136.75,69.85 136.75,70.08 136.83,70.16 136.98,70.16 137.06,70.24 137.06,70.92 136.88,71.1 136.6,71.1 136.53,71.02 v1(136.53,70.59)
DQ8+: length 81.3
  L08_SIG2 w0.076: v1(94.11,80.9) 94.51,80.9 94.61,81 94.61,81.25 94.99,81.64 95.59,81.64 96.42,82.46 97.71,82.46 98.04,82.13 98.04,80.63 98.22,80.45 108.8,80.45 108.94,80.59 108.94,80.98 108.78,81.14 99.17,81.14 98.88,81.43 98.88,82.15 99.19,82.46 118.94,82.46 119.18,82.7 138.09,82.7 138.65,82.14 138.65,81.84 138.89,81.6 139.19,81.6 139.78,81.01 139.78,79.25 139.34,78.82 139.08,78.82 138.56,78.29 138.56,75.49 138.01,74.94 137.68,74.94 137.36,74.63 137.36,72.76 137.51,72.61 137.72,72.61 137.79,72.69 v1(137.79,73.13)
DQ8-: length 81.3
  L08_SIG2 w0.076: v1(137.79,71.86) 137.79,72.29 137.72,72.37 137.41,72.37 137.12,72.66 137.12,74.73 137.58,75.18 137.91,75.18 138.32,75.59 138.32,78.39 138.98,79.06 139.24,79.06 139.53,79.35 139.53,79.91 139.4,80.05 139.4,80.35 139.53,80.49 139.53,80.91 139.09,81.36 138.79,81.36 138.4,81.74 138.4,82.04 137.99,82.46 119.28,82.46 119.04,82.22 99.29,82.22 99.12,82.05 99.12,81.53 99.27,81.38 108.88,81.38 109.18,81.08 109.18,80.49 108.9,80.21 98.12,80.21 97.8,80.53 97.8,82.03 97.61,82.22 97.35,82.22 97.24,82.11 97.24,82.03 97.13,81.92 96.97,81.92 96.86,82.03 96.86,82.11 96.75,82.22 96.52,82.22 95.69,81.39 95.13,81.39 94.88,81.14 94.88,81 94.98,80.9 v1(95.38,80.9)
DQ9+: length 81.3
  L05_SIG1 w0.076: v1(91.57,82.17) 91.97,82.17 92.11,82.02 92.11,81.84 91.87,81.6 91.31,81.6 90.92,81.2 90.92,80.54 91.08,80.38 91.08,78.94 90.81,78.66 90.81,70.83 98.2,63.44 99.65,63.44 99.8,63.28 99.8,62.75 100.09,62.46 100.83,62.46 101.12,62.75 101.12,63.28 101.27,63.44 101.8,63.44 101.96,63.28 101.96,62.75 102.25,62.46 102.98,62.46 103.28,62.75 103.28,63.28 103.43,63.44 103.96,63.44 104.12,63.28 104.12,62.75 104.41,62.46 105.14,62.46 105.44,62.75 105.44,63.28 105.59,63.44 106.12,63.44 106.27,63.28 106.27,62.75 106.57,62.46 107.3,62.46 107.6,62.75 107.6,63.28 107.75,63.44 108.28,63.44 108.43,63.28 108.43,62.75 108.73,62.46 109.46,62.46 109.75,62.75 109.75,63.28 109.91,63.44 110.44,63.44 110.59,63.28 110.59,62.75 110.89,62.46 111.62,62.46 111.91,62.75 111.91,63.28 112.07,63.44 112.6,63.44 112.75,63.28 112.75,62.75 113.05,62.46 113.78,62.46 114.07,62.75 114.07,63.28 114.23,63.44 114.76,63.44 114.91,63.28 114.91,62.75 115.2,62.46 115.94,62.46 116.23,62.75 116.23,63.28 116.38,63.44 116.92,63.44 117.07,63.28 117.07,62.75 117.36,62.46 118.1,62.46 118.39,62.75 118.39,63.28 118.54,63.44 119.08,63.44 119.23,63.28 119.23,62.75 119.52,62.46 120.26,62.46 120.55,62.75 120.55,63.28 120.7,63.44 121.24,63.44 121.39,63.28 121.39,62.75 121.68,62.46 122.42,62.46 122.71,62.75 122.71,63.28 122.86,63.44 123.39,63.44 123.55,63.28 123.55,62.75 123.84,62.46 124.57,62.46 124.87,62.75 124.87,63.28 125.02,63.44 125.55,63.44 125.71,63.28 125.71,62.75 126,62.46 126.73,62.46 127.03,62.75 127.03,63.28 127.18,63.44 127.71,63.44 127.94,63.21 127.94,62.68 128.16,62.46 128.89,62.46 129.19,62.75 129.19,63.28 129.34,63.44 130.38,63.44 132.13,65.19 132.13,67.26 131.86,67.53 131.52,67.53 131.44,67.61 v1(131.44,68.05)
DQ9-: length 81.2
  L05_SIG1 w0.076: v1(131.44,66.78) 131.44,67.21 131.52,67.29 131.76,67.29 131.89,67.16 131.89,66.36 131.82,66.29 131.54,66.29 131.47,66.22 131.47,66.04 131.55,65.96 131.81,65.96 131.89,65.89 131.89,65.29 130.71,64.11 130.51,64.11 130.4,64.01 130.4,63.8 130.28,63.68 129.24,63.68 128.94,63.38 128.94,62.85 128.79,62.7 128.26,62.7 128.18,62.78 128.18,63.31 127.81,63.68 127.08,63.68 126.79,63.38 126.79,62.85 126.63,62.7 126.1,62.7 125.95,62.85 125.95,63.38 125.65,63.68 124.92,63.68 124.63,63.38 124.63,62.85 124.47,62.7 123.94,62.7 123.79,62.85 123.79,63.38 123.49,63.68 122.76,63.68 122.47,63.38 122.47,62.85 122.31,62.7 121.78,62.7 121.63,62.85 121.63,63.38 121.34,63.68 120.6,63.68 120.31,63.38 120.31,62.85 120.16,62.7 119.62,62.7 119.47,62.85 119.47,63.38 119.18,63.68 118.44,63.68 118.15,63.38 118.15,62.85 118,62.7 117.46,62.7 117.31,62.85 117.31,63.38 117.02,63.68 116.28,63.68 115.99,63.38 115.99,62.85 115.84,62.7 115.3,62.7 115.15,62.85 115.15,63.38 114.86,63.68 114.12,63.68 113.83,63.38 113.83,62.85 113.68,62.7 113.15,62.7 112.99,62.85 112.99,63.38 112.7,63.68 111.97,63.68 111.67,63.38 111.67,62.85 111.52,62.7 110.99,62.7 110.83,62.85 110.83,63.38 110.54,63.68 109.81,63.68 109.51,63.38 109.51,62.85 109.36,62.7 108.83,62.7 108.68,62.85 108.68,63.38 108.38,63.68 107.65,63.68 107.35,63.38 107.35,62.85 107.2,62.7 106.67,62.7 106.52,62.85 106.52,63.38 106.22,63.68 105.49,63.68 105.2,63.38 105.2,62.85 105.04,62.7 104.51,62.7 104.36,62.85 104.36,63.38 104.06,63.68 103.33,63.68 103.04,63.38 103.04,62.85 102.88,62.7 102.35,62.7 102.2,62.85 102.2,63.38 101.9,63.68 101.17,63.68 100.88,63.38 100.88,62.85 100.72,62.7 100.19,62.7 100.04,62.85 100.04,63.38 99.75,63.68 99.19,63.68 98.98,63.88 98.73,63.88 98.53,63.68 98.3,63.68 91.69,70.28 91.69,70.59 91.59,70.69 91.28,70.69 91.05,70.93 91.05,78.56 91.33,78.84 91.33,80.48 91.16,80.64 91.16,81.1 91.41,81.36 91.97,81.36 92.35,81.74 92.35,82.05 92.48,82.17 v1(92.84,82.17)
DQ10+: length 81.3
  L05_SIG1 w0.076: v1(94.11,82.17) 94.55,82.17 94.62,82.25 94.62,82.52 94.98,82.88 95.66,82.88 96.11,82.42 96.11,81.76 95.73,81.38 92.76,81.38 92.3,80.92 92.3,80.33 92.42,80.21 92.42,79.4 92.2,79.19 92.2,71.7 98.56,65.34 99.34,65.34 100.35,64.33 100.56,64.33 100.71,64.48 100.71,65.05 101,65.34 101.74,65.34 102.03,65.05 102.03,64.48 102.18,64.33 102.72,64.33 102.87,64.48 102.87,65.05 103.16,65.34 103.9,65.34 104.19,65.05 104.19,64.48 104.34,64.33 104.88,64.33 105.03,64.48 105.03,65.05 105.32,65.34 106.06,65.34 106.35,65.05 106.35,64.48 106.5,64.33 107.03,64.33 107.19,64.48 107.19,65.05 107.48,65.34 108.21,65.34 108.51,65.05 108.51,64.48 108.66,64.33 109.19,64.33 109.35,64.48 109.35,65.05 109.64,65.34 110.37,65.34 110.67,65.05 110.67,64.48 110.82,64.33 111.35,64.33 111.51,64.48 111.51,65.05 111.8,65.34 112.53,65.34 112.83,65.05 112.83,64.48 112.98,64.33 113.51,64.33 113.66,64.48 113.66,65.05 113.96,65.34 114.69,65.34 114.99,65.05 114.99,64.48 115.14,64.33 115.67,64.33 115.82,64.48 115.82,65.05 116.12,65.34 116.85,65.34 117.14,65.05 117.14,64.48 117.3,64.33 117.83,64.33 117.98,64.48 117.98,65.05 118.28,65.34 119.01,65.34 119.3,65.05 119.3,64.48 119.46,64.33 119.99,64.33 120.14,64.48 120.14,65.05 120.43,65.34 121.17,65.34 121.46,65.05 121.46,64.48 121.61,64.33 122.15,64.33 122.3,64.48 122.3,65.05 122.59,65.34 123.33,65.34 123.62,65.05 123.62,64.48 123.77,64.33 124.26,64.33 124.46,64.53 124.46,64.81 124.91,65.25 125.55,65.25 126.52,64.29 128.47,64.29 130.48,66.29 130.48,68.05 131.24,68.8 132.64,68.8 132.72,68.88 v1(132.72,69.32)
DQ10-: length 81.3
  L05_SIG1 w0.076: v1(95.38,82.17) 94.94,82.17 94.86,82.25 94.86,82.42 95.08,82.64 95.56,82.64 95.87,82.32 95.87,81.86 95.63,81.62 95.07,81.62 94.91,81.79 94.55,81.79 94.39,81.62 92.66,81.62 92.06,81.02 92.06,80.23 92.18,80.11 92.18,79.5 91.96,79.29 91.96,71.6 98.46,65.1 99.24,65.1 100.25,64.08 100.66,64.08 100.95,64.38 100.95,64.95 101.1,65.1 101.64,65.1 101.79,64.95 101.79,64.38 102.08,64.08 102.82,64.08 103.11,64.38 103.11,64.95 103.26,65.1 103.8,65.1 103.95,64.95 103.95,64.38 104.24,64.08 104.98,64.08 105.27,64.38 105.27,64.95 105.42,65.1 105.96,65.1 106.11,64.95 106.11,64.38 106.4,64.08 107.13,64.08 107.43,64.38 107.43,64.95 107.58,65.1 108.11,65.1 108.27,64.95 108.27,64.38 108.56,64.08 109.29,64.08 109.59,64.38 109.59,64.95 109.74,65.1 110.27,65.1 110.43,64.95 110.43,64.38 110.72,64.08 111.45,64.08 111.75,64.38 111.75,64.95 111.9,65.1 112.43,65.1 112.58,64.95 112.58,64.38 112.88,64.08 113.61,64.08 113.91,64.38 113.91,64.95 114.06,65.1 114.59,65.1 114.74,64.95 114.74,64.38 115.04,64.08 115.77,64.08 116.06,64.38 116.06,64.95 116.22,65.1 116.75,65.1 116.9,64.95 116.9,64.38 117.2,64.08 117.93,64.08 118.22,64.38 118.22,64.95 118.38,65.1 118.91,65.1 119.06,64.95 119.06,64.38 119.36,64.08 120.09,64.08 120.38,64.38 120.38,64.95 120.53,65.1 121.07,65.1 121.22,64.95 121.22,64.38 121.51,64.08 122.25,64.08 122.54,64.38 122.54,64.95 122.69,65.1 123.23,65.1 123.38,64.95 123.38,64.38 123.67,64.08 124.36,64.08 124.7,64.43 124.7,64.71 125.01,65.01 125.45,65.01 126.42,64.05 128.57,64.05 130.72,66.19 130.72,67.18 130.8,67.26 130.86,67.26 130.94,67.34 130.94,67.57 130.86,67.64 130.8,67.64 130.72,67.72 130.72,67.95 131.34,68.56 132.64,68.56 132.72,68.48 v1(132.72,68.05)
DQ11+: length 81.2
  L05_SIG1 w0.076: v1(136.53,68.05) 136.53,67.61 136.6,67.53 136.9,67.53 137.21,67.22 137.21,66.53 136.8,66.12 136.25,66.12 135.85,66.52 135.85,66.77 135.25,67.37 134.99,67.37 134.59,67.77 134.59,68.07 134.14,68.53 133.73,68.53 133.43,68.22 133.43,64.86 130.05,61.48 123.06,61.48 122.96,61.38 122.96,60.92 122.65,60.62 121.95,60.62 121.64,60.92 121.64,61.38 121.49,61.53 120.95,61.53 120.8,61.38 120.8,60.92 120.51,60.63 119.77,60.63 119.48,60.92 119.48,61.38 119.33,61.53 118.79,61.53 118.64,61.38 118.64,60.92 118.35,60.63 117.61,60.63 117.32,60.92 117.32,61.38 117.17,61.53 116.64,61.53 116.48,61.38 116.48,60.92 116.19,60.63 115.46,60.63 115.16,60.92 115.16,61.38 115.01,61.53 97.79,61.53 89.64,69.69 89.64,81.18 91.41,82.96 93.21,82.96 93.35,83.1 93.35,83.36 93.28,83.44 v1(92.84,83.44)
DQ11-: length 81.2
  L05_SIG1 w0.076: v1(94.11,83.44) 93.67,83.44 93.59,83.36 93.59,83 93.31,82.72 91.51,82.72 89.88,81.08 89.88,69.79 90.09,69.57 90.25,69.57 90.28,69.61 90.44,69.61 90.55,69.49 90.55,69.34 90.52,69.3 90.52,69.15 97.89,61.77 115.11,61.77 115.4,61.48 115.4,61.02 115.56,60.87 116.09,60.87 116.24,61.02 116.24,61.48 116.54,61.77 117.27,61.77 117.56,61.48 117.56,61.02 117.72,60.87 118.25,60.87 118.4,61.02 118.4,61.48 118.69,61.77 119.43,61.77 119.72,61.48 119.72,61.02 119.87,60.87 120.41,60.87 120.56,61.02 120.56,61.48 120.85,61.77 121.59,61.77 121.88,61.48 121.88,61.02 122.05,60.86 122.55,60.86 122.72,61.02 122.72,61.48 122.96,61.72 129.95,61.72 130.18,61.96 130.18,62.11 130.15,62.15 130.15,62.3 130.26,62.42 130.42,62.42 130.45,62.38 130.61,62.38 133.18,64.96 133.18,68.32 133.63,68.77 134.24,68.77 134.84,68.17 134.84,67.87 135.09,67.61 135.35,67.61 135.51,67.45 135.67,67.45 135.83,67.62 135.99,67.62 136.1,67.5 136.1,67.35 135.94,67.18 135.94,67.03 136.09,66.87 136.09,66.62 136.35,66.36 136.7,66.36 136.97,66.63 136.97,67.12 136.8,67.29 136.6,67.29 136.53,67.21 v1(136.53,66.78)
DQD0+: length 81.3
  L10_SIG3 w0.076: v1(137.79,104.88) 137.79,104.44 137.78,104.43 137.77,104.43 137.7,104.36 123.32,104.36 119.3,100.33 119.3,100.02 119.95,99.37 119.95,99.16 119.57,98.78 119.36,98.78 118.76,99.38 118.34,99.38 117.82,98.86 117.82,98.44 118.42,97.84 118.42,97.63 118.04,97.25 117.83,97.25 117.23,97.85 116.81,97.85 116.29,97.33 116.29,96.92 116.89,96.32 116.89,96.1 116.52,95.72 116.3,95.72 115.7,96.32 115.29,96.32 114.77,95.8 114.77,95.39 115.37,94.79 115.37,94.57 114.99,94.2 113.16,94.2 101.51,82.55 98.07,82.55 97.66,82.96 89.92,82.96 88.93,81.97 85.09,81.97 84.72,81.59 84.72,81.21 84.45,80.94 84.06,80.94 83.69,80.57 83.69,80.02 81.97,78.3 81.97,74.01 82.19,73.79 82.6,73.79 82.68,73.72 v1(82.68,73.28)
DQD0-: length 81.2
  L10_SIG3 w0.076: v1(137.79,103.61) 137.79,104.04 137.72,104.11 123.42,104.11 119.54,100.23 119.54,100.13 120.19,99.47 120.19,99.06 119.67,98.54 119.26,98.54 118.66,99.14 118.44,99.14 118.06,98.76 118.06,98.54 118.66,97.94 118.66,97.53 118.14,97.01 117.73,97.01 117.13,97.61 116.91,97.61 116.54,97.23 116.54,97.02 117.13,96.42 117.13,96 116.62,95.48 116.2,95.48 115.6,96.08 115.39,96.08 115.01,95.7 115.01,95.49 115.61,94.89 115.61,94.47 115.09,93.96 113.26,93.96 101.61,82.31 97.97,82.31 97.56,82.72 90.02,82.72 89.03,81.72 85.19,81.72 84.96,81.49 84.96,81.11 84.55,80.7 84.16,80.7 83.93,80.47 83.93,79.92 82.83,78.81 82.83,78.65 82.92,78.56 82.92,78.4 82.81,78.29 82.65,78.29 82.56,78.38 82.4,78.38 82.21,78.2 82.21,75.46 82.46,75.21 82.46,75.1 82.21,74.85 82.21,74.11 82.29,74.03 82.6,74.03 82.68,74.11 v1(82.68,74.55)
DQD1+: length 81.1
  L10_SIG3 w0.076: v1(82.68,75.82) 82.68,76.26 82.75,76.33 82.96,76.33 83.53,76.9 83.53,78.34 83.94,78.75 84.23,78.75 84.4,78.91 84.4,79.2 84.58,79.39 85.26,79.39 85.94,80.07 85.94,80.52 86.13,80.71 86.59,80.71 86.73,80.57 86.88,80.57 87.02,80.71 89.69,80.71 90.36,81.38 90.81,81.38 90.94,81.25 91.13,81.25 91.26,81.38 105.09,81.38 106.05,82.34 106.05,83.25 105.75,83.54 105.75,84.12 106.13,84.5 106.34,84.5 107.08,83.76 107.5,83.76 108.02,84.28 108.02,84.7 107.28,85.43 107.28,85.65 107.65,86.03 107.87,86.03 108.54,85.36 109.09,85.36 109.58,85.84 109.58,86.19 108.8,86.96 108.8,87.18 109.18,87.56 109.4,87.56 110.14,86.82 110.55,86.82 111.05,87.31 111.05,87.77 110.33,88.49 110.33,88.71 110.71,89.08 110.92,89.08 111.66,88.34 112.08,88.34 112.6,88.86 112.6,89.28 111.86,90.02 111.86,90.23 112.24,90.61 112.45,90.61 113.19,89.87 113.61,89.87 114.13,90.39 114.13,90.81 113.39,91.54 113.39,91.76 113.76,92.14 113.98,92.14 114.45,91.67 115.4,91.67 124.19,100.46 124.74,100.46 124.92,100.28 125.15,100.28 125.25,100.38 132.96,100.38 133.25,100.09 133.25,99.57 133.1,99.42 133.1,99.16 133.25,99.01 133.25,98.41 132.85,98.01 131.52,98.01 131.44,98.09 v1(131.44,98.53)
DQD1-: length 81.3
  L10_SIG3 w0.076: v1(82.68,77.09) 82.68,76.65 82.75,76.57 82.86,76.57 83.29,77 83.29,78.44 84.48,79.63 85.16,79.63 85.7,80.17 85.7,80.62 86.03,80.95 89.59,80.95 90.26,81.62 104.99,81.62 105.8,82.44 105.8,83.15 105.51,83.44 105.51,84.22 106.03,84.74 106.44,84.74 107.18,84 107.4,84 107.77,84.38 107.77,84.6 107.04,85.33 107.04,85.75 107.55,86.27 107.97,86.27 108.64,85.6 108.99,85.6 109.33,85.94 109.33,86.09 108.56,86.86 108.56,87.28 109.08,87.8 109.5,87.8 110.24,87.06 110.45,87.06 110.81,87.41 110.81,87.67 110.09,88.39 110.09,88.81 110.61,89.32 111.02,89.32 111.76,88.59 111.98,88.59 112.36,88.96 112.36,89.18 111.62,89.92 111.62,90.33 112.14,90.85 112.55,90.85 113.29,90.11 113.51,90.11 113.88,90.49 113.88,90.71 113.15,91.44 113.15,91.86 113.66,92.38 114.08,92.38 114.55,91.91 115.3,91.91 124.09,100.7 125.07,100.7 125.15,100.62 133.06,100.62 133.49,100.19 133.49,98.31 132.95,97.77 131.52,97.77 131.44,97.69 v1(131.44,97.26)
DQD2+: length 81.3
  L10_SIG3 w0.076: v1(83.95,74.55) 83.95,74.99 83.87,75.06 83.66,75.06 83.25,75.48 83.25,76.11 83.68,76.54 83.9,76.54 84.48,77.12 84.48,77.3 86.98,79.81 90.81,79.81 91.45,80.45 107.78,80.45 108.77,81.44 108.77,81.65 108.26,82.16 108.26,82.58 108.78,83.1 109.19,83.1 109.7,82.59 109.92,82.59 110.29,82.96 110.29,83.18 109.78,83.69 109.78,84.1 110.3,84.62 110.72,84.62 111.23,84.11 111.44,84.11 111.82,84.49 111.82,84.71 111.3,85.23 111.3,85.62 111.79,86.11 112.29,86.11 112.76,85.64 112.97,85.64 113.35,86.02 113.35,86.23 112.84,86.74 112.84,87.16 113.36,87.68 113.77,87.68 114.28,87.17 114.5,87.17 114.88,87.55 114.88,87.76 114.37,88.27 114.37,88.69 114.89,89.21 115.3,89.21 115.81,88.7 116.03,88.7 116.4,89.07 116.4,89.29 115.89,89.8 115.89,90.22 116.41,90.73 116.83,90.73 117.34,90.22 117.55,90.22 117.93,90.6 117.93,90.82 117.42,91.33 117.42,91.74 117.94,92.26 118.36,92.26 118.87,91.75 119.08,91.75 119.46,92.13 119.46,92.34 118.95,92.85 118.95,93.27 119.47,93.79 119.88,93.79 120.39,93.28 120.61,93.28 120.99,93.66 120.99,93.87 120.48,94.38 120.48,94.8 121,95.32 121.41,95.32 121.92,94.81 122.14,94.81 122.52,95.18 122.52,95.4 122,95.91 122,96.33 122.52,96.84 122.94,96.84 123.45,96.33 123.66,96.33 124.04,96.71 124.04,96.93 123.53,97.44 123.53,97.85 124.05,98.37 124.47,98.37 124.76,98.08 125.41,98.08 126.61,99.28 132.64,99.28 132.72,99.36 v1(132.72,99.8)
DQD2-: length 81.1
  L10_SIG3 w0.076: v1(83.95,75.82) 83.95,75.38 83.87,75.3 83.76,75.3 83.49,75.58 83.49,76.01 83.78,76.3 84,76.3 84.17,76.46 84.27,76.46 84.39,76.35 84.5,76.35 84.66,76.51 84.66,76.62 84.54,76.73 84.54,76.84 84.72,77.02 84.72,77.2 87.08,79.57 87.33,79.57 87.49,79.4 87.82,79.4 87.99,79.57 90.91,79.57 91.55,80.21 107.88,80.21 109.01,81.34 109.01,81.75 108.5,82.26 108.5,82.48 108.88,82.85 109.09,82.85 109.6,82.34 110.02,82.34 110.54,82.86 110.54,83.28 110.03,83.79 110.03,84 110.4,84.38 110.62,84.38 111.13,83.87 111.54,83.87 112.06,84.39 112.06,84.81 111.54,85.33 111.54,85.52 111.89,85.86 112.19,85.86 112.66,85.4 113.07,85.4 113.59,85.92 113.59,86.33 113.08,86.84 113.08,87.06 113.46,87.44 113.67,87.44 114.18,86.93 114.6,86.93 115.12,87.45 115.12,87.86 114.61,88.37 114.61,88.59 114.99,88.97 115.2,88.97 115.71,88.45 116.13,88.45 116.65,88.97 116.65,89.39 116.14,89.9 116.14,90.12 116.51,90.49 116.73,90.49 117.24,89.98 117.65,89.98 118.17,90.5 118.17,90.92 117.66,91.43 117.66,91.64 118.04,92.02 118.26,92.02 118.77,91.51 119.18,91.51 119.7,92.03 119.7,92.44 119.19,92.95 119.19,93.17 119.57,93.55 119.78,93.55 120.29,93.04 120.71,93.04 121.23,93.56 121.23,93.97 120.72,94.48 120.72,94.7 121.1,95.08 121.31,95.08 121.82,94.56 122.24,94.56 122.76,95.08 122.76,95.5 122.25,96.01 122.25,96.23 122.62,96.6 122.84,96.6 123.35,96.09 123.76,96.09 124.28,96.61 124.28,97.03 123.77,97.54 123.77,97.75 124.15,98.13 124.37,98.13 124.66,97.84 125.51,97.84 126.71,99.04 132.64,99.04 132.72,98.96 v1(132.72,98.53)
DQD3+: length 81.7
  L10_SIG3 w0.076: v1(85.22,73.28) 85.22,73.68 85.32,73.78 85.46,73.78 85.7,73.54 85.7,72.71 93.05,65.35 116.99,65.35 134.84,83.2 134.84,83.46 135.08,83.71 135.34,83.71 136.11,84.47 136.11,84.73 136.35,84.98 136.61,84.98 137.19,85.55 137.19,85.81 137.62,86.25 137.88,86.25 138.65,87.01 138.65,87.27 138.89,87.52 139.15,87.52 139.89,88.26 139.89,96.1 139.34,96.65 138.62,96.65 137.25,98.01 136.6,98.01 136.53,98.09 v1(136.53,98.53)
DQD3-: length 81.6
  L10_SIG3 w0.076: v1(136.53,97.26) 136.53,97.69 136.6,97.77 137.15,97.77 137.94,96.98 137.94,96.88 137.9,96.83 137.9,96.67 138.01,96.56 138.17,96.56 138.21,96.61 138.32,96.61 138.52,96.41 139.24,96.41 139.65,96 139.65,90.61 139.57,90.53 139.5,90.53 139.4,90.43 139.4,90.25 139.5,90.15 139.57,90.15 139.65,90.08 139.65,88.36 139.05,87.76 138.79,87.76 138.4,87.37 138.4,87.11 137.78,86.49 137.52,86.49 136.94,85.91 136.94,85.65 136.51,85.22 136.25,85.22 135.86,84.83 135.86,84.57 135.24,83.95 134.98,83.95 134.59,83.56 134.59,83.3 117.38,66.08 117.22,66.08 117.13,66 117.13,65.84 116.89,65.6 93.15,65.6 85.94,72.81 85.94,73.68 85.57,74.05 85.32,74.05 85.22,74.15 v1(85.22,74.55)
DQD4+: length 81.2
  L10_SIG3 w0.076: v1(137.79,99.8) 137.79,99.36 137.87,99.28 138.13,99.28 138.26,99.41 138.26,100.05 138.04,100.28 136.78,100.28 136.6,100.1 136.6,99.99 136.78,99.82 136.78,99.64 136.68,99.54 136.52,99.54 136.33,99.73 136.23,99.73 135.45,98.95 135.08,98.95 134.84,98.7 134.84,98.39 134.12,97.68 133.81,97.68 133.57,97.43 133.57,97.12 132.93,96.48 126.22,96.48 125.78,96.04 125.78,95.47 126.35,94.9 126.35,94.48 125.83,93.96 125.41,93.96 124.7,94.68 124.48,94.68 124.11,94.3 124.11,94.09 124.69,93.5 124.69,92.83 117.59,85.72 117.18,85.72 116.38,86.53 116.16,86.53 115.78,86.16 115.78,85.94 116.59,85.14 116.59,84.72 116.07,84.2 115.65,84.2 114.85,85.01 114.63,85.01 114.26,84.63 114.26,84.41 115.06,83.61 115.06,83.2 114.54,82.68 114.12,82.68 113.32,83.48 113.11,83.48 112.73,83.1 112.73,82.89 113.53,82.08 113.53,81.67 113.02,81.15 112.59,81.15 111.79,81.95 111.58,81.95 111.2,81.57 111.2,81.36 112,80.56 112,80.14 110.65,78.79 87.45,78.79 85.99,77.33 85.99,76.57 85.76,76.33 85.29,76.33 85.22,76.26 v1(85.22,75.82)
DQD4-: length 81.3
  L10_SIG3 w0.076: v1(137.79,98.53) 137.79,98.96 137.87,99.04 138.23,99.04 138.51,99.31 138.51,100.15 138.14,100.52 136.68,100.52 135.35,99.19 134.98,99.19 134.59,98.8 134.59,98.49 134.02,97.92 133.71,97.92 133.32,97.53 133.32,97.22 132.83,96.72 126.12,96.72 125.54,96.14 125.54,95.37 126.11,94.8 126.11,94.58 125.73,94.21 125.51,94.21 124.8,94.92 124.38,94.92 123.86,94.4 123.86,93.99 124.45,93.4 124.45,92.93 117.49,85.97 117.29,85.97 116.48,86.77 116.06,86.77 115.54,86.26 115.54,85.84 116.34,85.04 116.34,84.82 115.97,84.44 115.75,84.44 114.95,85.25 114.53,85.25 114.01,84.73 114.01,84.31 114.82,83.51 114.82,83.3 114.44,82.92 114.22,82.92 113.42,83.72 113.01,83.72 112.49,83.2 112.49,82.79 113.29,81.98 113.29,81.77 112.92,81.39 112.69,81.39 111.89,82.19 111.48,82.19 110.96,81.67 110.96,81.26 111.76,80.46 111.76,80.24 110.55,79.03 87.35,79.03 85.75,77.43 85.75,76.67 85.66,76.57 85.29,76.57 85.22,76.65 v1(85.22,77.09)
